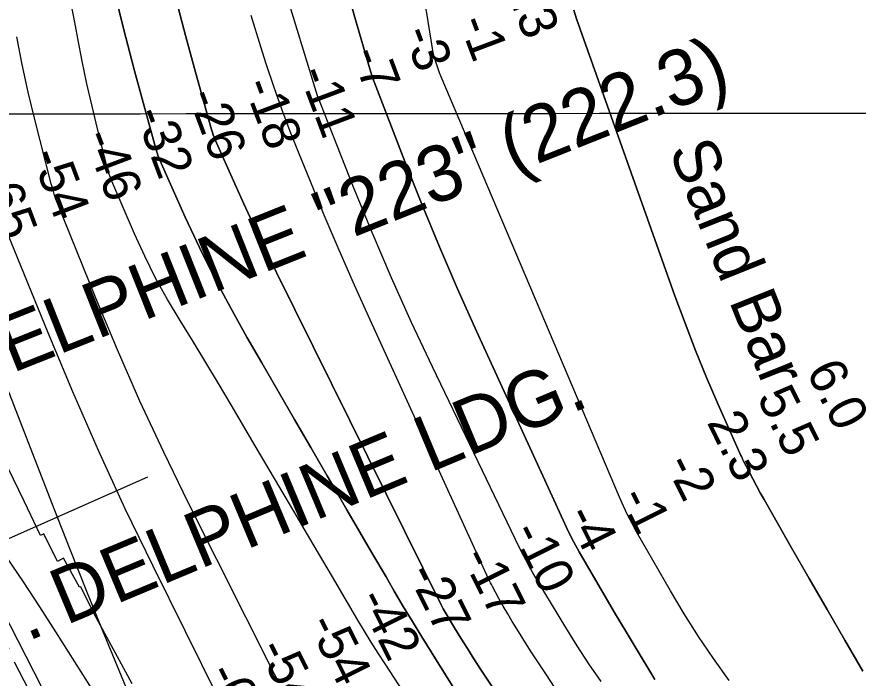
# Model space of a CAD drawing. Extents: x 3297753 to 3335611, y 652252 to 677623.
# Drawn here: x 3308869 to 3310374, y 671780 to 672962 of the extents above; entities that cross this region are included whole.
import ezdxf

# ---------------------------------------------------------------- set-up
doc = ezdxf.new("R2010")
doc.units = 0
for name, color, linetype in [('V-CHAN-NAID', 7, 'Continuous'), ('V-GRID-MAJR', 7, 'Continuous'), ('V-RIVR-EDGE', 7, 'Continuous'), ('V-RIVR-IDEN', 7, 'Continuous'), ('V-RIVR-RANG', 7, 'Continuous'), ('V-RRAP-RVMT', 7, 'Continuous'), ('V-TOPO-DPTH', 7, 'Continuous'), ('V-TOPO-GNAM-IDEN', 7, 'Continuous'), ('V-TOPO-MAJR', 7, 'Continuous'), ('V-TOPO-MINR', 7, 'Continuous'), ('V-TOPO-WATR', 7, 'Continuous')]:
    doc.layers.add(name, color=color, linetype=linetype)

msp = doc.modelspace()

# ---------------------------------------------------------------- linework, layer by layer
at = {"layer": 'V-GRID-MAJR'}
msp.add_spline([(3301861.4, 672784.2), (3307118.4, 672787.6), (3312375.4, 672791.8), (3317632.5, 672796.8), (3322889.5, 672802.5), (3328146.5, 672809), (3333403.5, 672816.3)], degree=3, dxfattribs=at)
at = {"layer": 'V-RIVR-EDGE'}
msp.add_spline([(3307850.6, 675821), (3307850.8, 675819.3), (3307852.4, 675798.5), (3307852.3, 675791.1), (3307856.9, 675791.5), (3307860.2, 675784), (3307858.1, 675766.6), (3307858, 675745.9), (3307859.7, 675743.8), (3307863.4, 675743), (3307863.4, 675739.6), (3307862.9, 675721), (3307866.2, 675694), (3307864.5, 675668.3), (3307864.8, 675653.4), (3307866, 675632.3), (3307866, 675608.2), (3307860.9, 675578), (3307855, 675536.2), (3307852, 675491), (3307848.6, 675457.4), (3307845.6, 675420.9), (3307843.1, 675401.9), (3307841.8, 675387.8), (3307842.2, 675364.6), (3307841.7, 675337.2), (3307844.1, 675320.6), (3307845.7, 675299.9), (3307849, 675263), (3307851.4, 675230.3), (3307851.7, 675205), (3307854.1, 675179.3), (3307857, 675154), (3307856.5, 675138.2), (3307855.7, 675135.8), (3307856.1, 675118.3), (3307855.6, 675111.7), (3307854.4, 675096), (3307852.6, 675077.7), (3307852.2, 675054.1), (3307855.4, 675031.7), (3307862.4, 674991.5), (3307864.8, 674962.5), (3307868.4, 674926), (3307870, 674906.1), (3307872.5, 674875), (3307874.1, 674859.3), (3307876.5, 674843.5), (3307878.9, 674816.1), (3307882.5, 674757.7), (3307886.1, 674712.5), (3307885.7, 674704.2), (3307884.5, 674698), (3307884.4, 674691.8), (3307887.3, 674680.2), (3307887.3, 674669), (3307887.3, 674658.2), (3307885.6, 674651.2), (3307881, 674644.1), (3307881, 674640), (3307886.3, 674626.3), (3307890, 674605.5), (3307895.8, 674578.6), (3307899.4, 674550.8), (3307909.3, 674510.6), (3307914.6, 674482), (3307918.3, 674453.8), (3307918.2, 674440.5), (3307919.9, 674433.9), (3307927.3, 674423.1), (3307927.3, 674417.7), (3307927.2, 674404), (3307928.5, 674400.3), (3307931.8, 674393.2), (3307935.1, 674376.6), (3307944.5, 674357.6), (3307954.9, 674337.2), (3307963.9, 674316.1), (3307975.4, 674271.7), (3307986.5, 674225.2), (3308000.1, 674178.8), (3308007.4, 674148.9), (3308015.2, 674108.3), (3308020.5, 674078.4), (3308024.2, 674072.2), (3308025, 674059.3), (3308025.4, 674039.4), (3308027.8, 673997.2), (3308030.6, 673971.5), (3308027.7, 673955.3), (3308027.2, 673943.3), (3308027.6, 673935.8), (3308029.7, 673925.4), (3308035.5, 673911.8), (3308035.4, 673899.3), (3308034.1, 673873.2), (3308036.1, 673851.2), (3308038.5, 673818.9), (3308041, 673799), (3308046.8, 673788.2), (3308050.5, 673778.3), (3308048.8, 673772.5), (3308048.8, 673761.3), (3308053.7, 673740.5), (3308060.7, 673711.1), (3308069.7, 673678.7), (3308069.7, 673665.1), (3308067.1, 673653.5), (3308067.6, 673650.1), (3308072.9, 673649.3), (3308077.9, 673648.9), (3308080, 673646.4), (3308086.5, 673608.6), (3308091.8, 673582.1), (3308104.6, 673536.5), (3308114.8, 673495), (3308121.4, 673461), (3308123.8, 673446.1), (3308128, 673436.1), (3308140.3, 673406.2), (3308148.9, 673377.2), (3308153, 673357.7), (3308158.3, 673321.2), (3308169, 673273.1), (3308189.1, 673188.1), (3308196.9, 673150.4), (3308208, 673103.9), (3308212, 673079.5), (3308214.1, 673060), (3308216.5, 673045), (3308219, 673035.9), (3308226, 673025.5), (3308228.5, 673016), (3308228.4, 673002.3), (3308230.5, 672996.9), (3308235, 672992.8), (3308235, 672984.5), (3308237.5, 672972.9), (3308242, 672953.4), (3308247.3, 672933.1), (3308253.9, 672910.7), (3308257.6, 672901.5), (3308263.8, 672890.3), (3308276.2, 672865), (3308277.4, 672856.3), (3308278.6, 672850.1), (3308283.2, 672844.3), (3308286.1, 672839.7), (3308286, 672832.2), (3308285.6, 672819), (3308288.5, 672812.3), (3308293.8, 672800.3), (3308303.7, 672777.9), (3308309.9, 672762.5), (3308316.1, 672743), (3308316.4, 672725.6), (3308318.1, 672723.1), (3308323.1, 672717.3), (3308327.6, 672706.1), (3308331.7, 672690.4), (3308330.8, 672679.6), (3308330.4, 672672.1), (3308332.5, 672667.2), (3308337.4, 672658.4), (3308343.6, 672642.7), (3308347.7, 672625.3), (3308355.9, 672595.4), (3308355.9, 672584.6), (3308357.5, 672579.6), (3308362.1, 672570.9), (3308366.6, 672563.5), (3308376.1, 672534), (3308399.6, 672478.4), (3308411.5, 672452.7), (3308418.5, 672435.2), (3308421.8, 672418.7), (3308423, 672410), (3308425.5, 672403.7), (3308428.8, 672397.5), (3308430, 672387.6), (3308434.9, 672375.5), (3308444.4, 672344.8), (3308450.6, 672327), (3308456.8, 672320.8), (3308459.7, 672312.9), (3308465.4, 672288), (3308467.4, 672268.1), (3308473.2, 672249), (3308476.1, 672236.6), (3308485.9, 672214.2), (3308490.1, 672198.8), (3308495.9, 672201.7), (3308496.7, 672193), (3308499.1, 672161.9), (3308505.2, 672134.5), (3308513.9, 672107.6), (3308522.5, 672084.8), (3308527.9, 672082.3), (3308536.2, 672087.2), (3308540.8, 672086.8), (3308539.5, 672083.9), (3308535.8, 672077.7), (3308534.9, 672067.7), (3308534.5, 672059.4), (3308532, 672050.7), (3308533.2, 672047.4), (3308536.9, 672037.9), (3308550.9, 672008.4), (3308564.9, 671974.4), (3308569.9, 671959.5), (3308576.5, 671954.9), (3308585.1, 671932.5), (3308595.9, 671910.5), (3308604.9, 671895.1), (3308605.8, 671888.5), (3308607.8, 671885.2), (3308610.7, 671881), (3308616.5, 671862.8), (3308627.6, 671838.7), (3308640.4, 671816.3), (3308661, 671765.3), (3308673, 671740.8), (3308685.3, 671715.5), (3308698.5, 671692.2), (3308700.2, 671685.6), (3308711.3, 671658.2), (3308728.2, 671627.9), (3308743.1, 671603), (3308758.3, 671575.6), (3308772, 671554.8), (3308775.3, 671548.6), (3308783.1, 671536.2), (3308790.5, 671522.9), (3308793.4, 671519.6), (3308797.2, 671517.1), (3308801.3, 671511.2), (3308803.8, 671502.9), (3308810.8, 671502.1), (3308815.8, 671499.2), (3308833.5, 671474.3), (3308845.1, 671458.5), (3308857.1, 671443.5), (3308870.7, 671429), (3308882.7, 671418.6), (3308908.8, 671397), (3308930.3, 671375.4), (3308944.3, 671361.3), (3308952.6, 671346.7), (3308960.4, 671336.8), (3308966.2, 671331.8), (3308972.8, 671328.9), (3308985.6, 671307.3), (3309001.7, 671282.4), (3309010.8, 671271.6), (3309010.8, 671268.3), (3309008.3, 671266.2), (3309011.6, 671262), (3309018.7, 671250.8), (3309024.8, 671237.1), (3309035.1, 671212.2), (3309059.5, 671169.1), (3309066.5, 671150.8), (3309067.7, 671140.5), (3309071.8, 671135.9), (3309077.2, 671128.4), (3309078.4, 671123), (3309078.4, 671117.6), (3309082.1, 671111.4), (3309089.1, 671092.7), (3309098.6, 671073.2), (3309111.4, 671045), (3309116.4, 671032.2), (3309123.3, 671011), (3309128.7, 670995.6), (3309133.2, 670984.9), (3309144, 670967.4), (3309159.7, 670945.4), (3309169.2, 670933.4), (3309182, 670924.2), (3309188.2, 670917.2), (3309197.7, 670902.2), (3309217.1, 670874.8), (3309231.6, 670859), (3309239.8, 670845.3), (3309244.8, 670840.8), (3309252.2, 670835.3), (3309260.5, 670831.2), (3309275.4, 670817.1), (3309282.4, 670810.4), (3309290.7, 670800), (3309303.1, 670788.4), (3309315.9, 670775.5), (3309335.3, 670751), (3309344.4, 670736.5), (3309351, 670726.5), (3309360.1, 670721.5), (3309375.8, 670704.9), (3309390.7, 670688.7), (3309403.1, 670668.8), (3309415.5, 670646.8), (3309426.7, 670635.1), (3309442.8, 670618.5), (3309454.3, 670603.2), (3309462.2, 670588.6), (3309470.9, 670575.3), (3309476.6, 670563.3), (3309487.4, 670558.3), (3309488.6, 670554.6), (3309489.4, 670550.8), (3309494.8, 670544.2), (3309506.8, 670533.4), (3309523.8, 670518.8), (3309530, 670506), (3309538.6, 670484.8), (3309549.7, 670453.7), (3309551.3, 670440.9), (3309555.5, 670430.9), (3309568.7, 670408.9), (3309577.3, 670396), (3309581.5, 670386.5), (3309581.5, 670383.2), (3309578.6, 670379.9), (3309576.9, 670374.9), (3309582.2, 670364.1), (3309594.6, 670336.7), (3309604.5, 670308.9), (3309606.9, 670296.1), (3309614.4, 670284.8), (3309627.2, 670267), (3309635.5, 670261.6), (3309639.2, 670259.9), (3309638.7, 670250), (3309639.5, 670236.3), (3309641.2, 670228), (3309644.9, 670221.4), (3309656.5, 670208.1), (3309664.3, 670195.6), (3309663.5, 670188.2), (3309663.8, 670176.1), (3309668, 670166.2), (3309673.3, 670159.9), (3309684.1, 670142.9), (3309690.7, 670126.3), (3309700.1, 670102.7), (3309716.7, 670076.5)], degree=3, dxfattribs=at)
at = {"layer": 'V-RIVR-RANG'}
msp.add_line((3307750.1, 671541.1), (3309103.4, 672140.2), dxfattribs=at)
at = {"layer": 'V-RRAP-RVMT'}
for p, q in [((3308882.2, 672096.3), (3308820.5, 672223)), ((3308911.7, 672035.2), (3308882.2, 672096.3)), ((3308917.5, 672038), (3308911.7, 672035.2)), ((3308941.7, 671988.6), (3308917.5, 672038)), ((3308952.7, 671994.7), (3308941.7, 671988.6)), ((3308981.3, 671942.4), (3308952.7, 671994.7)), ((3308983.6, 671943.5), (3308981.3, 671942.4)), ((3309007.2, 671895.1), (3308983.6, 671943.5)), ((3309075.6, 671769.9), (3309007.2, 671895.1))]:
    msp.add_line(p, q, dxfattribs=at)
at = {"layer": 'V-TOPO-DPTH'}
for points in [[(3309041.7, 673017), (3309060.1, 672941.1), (3309079.8, 672865.4), (3309115.2, 672734.9), (3309118.2, 672724.8), (3309121.6, 672714.7), (3309125.4, 672704.8), (3309129.5, 672695.1), (3309170.3, 672604.3), (3309195.9, 672549.7), (3309222.6, 672495.6), (3309251, 672442.4), (3309280.5, 672389.8), (3309307.4, 672343.5), (3309336.7, 672293.1), (3309365.9, 672242.7), (3309395.1, 672192.3), (3309424.3, 672141.9), (3309436.2, 672121.3), (3309459.4, 672081.2), (3309482.7, 672041.1), (3309506.1, 672001), (3309529.5, 671960.9), (3309544.1, 671935.8), (3309560.3, 671908.4), (3309576.7, 671881.1), (3309593.3, 671853.9), (3309610, 671826.9), (3309979.7, 671235.6)], [(3309979.7, 671235.6), (3309610, 671826.9), (3309593.3, 671853.9), (3309576.7, 671881.1), (3309560.3, 671908.4), (3309544.1, 671935.8), (3309529.5, 671960.9), (3309506.1, 672001), (3309482.7, 672041.1), (3309459.4, 672081.2), (3309436.2, 672121.3), (3309424.3, 672141.9), (3309395.1, 672192.3), (3309365.9, 672242.7), (3309336.7, 672293.1), (3309307.4, 672343.5), (3309280.5, 672389.8), (3309251, 672442.4), (3309222.6, 672495.6), (3309195.9, 672549.7), (3309170.3, 672604.3), (3309129.5, 672695.1), (3309125.4, 672704.8), (3309121.6, 672714.7), (3309118.2, 672724.8), (3309115.2, 672734.9), (3309079.8, 672865.4), (3309060.1, 672941.1), (3309041.7, 673017)], [(3309459.4, 673013), (3309473.9, 672961.1), (3309500.3, 672869.5), (3309502.1, 672863.5), (3309504, 672857.6), (3309506, 672851.7), (3309508.2, 672845.9), (3309563.1, 672703.9), (3309593.5, 672627.4), (3309624.9, 672551.2), (3309657.6, 672475.7), (3309691.2, 672400.6), (3309846.4, 672062.2), (3309855.6, 672043.1), (3309865.1, 672024.2), (3309875.1, 672005.6), (3309885.6, 671987.1), (3309936.6, 671900.4), (3309973.3, 671839), (3310010.5, 671777.9)], [(3310010.5, 671777.9), (3309973.3, 671839), (3309936.6, 671900.4), (3309885.6, 671987.1), (3309875.1, 672005.6), (3309865.1, 672024.2), (3309855.6, 672043.1), (3309846.4, 672062.2), (3309691.2, 672400.6), (3309657.6, 672475.7), (3309624.9, 672551.2), (3309593.5, 672627.4), (3309563.1, 672703.9), (3309508.2, 672845.9), (3309506, 672851.7), (3309504, 672857.6), (3309502.1, 672863.5), (3309500.3, 672869.5), (3309473.9, 672961.1), (3309459.4, 673013)], [(3309155.1, 672988.1), (3309170.8, 672928.8), (3309186.9, 672869.6), (3309215.4, 672766.5), (3309217.7, 672759), (3309220.2, 672751.5), (3309223, 672744.2), (3309226, 672736.9), (3309256.5, 672668.8), (3309275.3, 672627.7), (3309294.3, 672586.7), (3309313.8, 672545.9), (3309333.6, 672505.3), (3309628, 671911.1), (3309629.8, 671907.6), (3309631.7, 671904.2), (3309652.1, 671870.1), (3309663.5, 671851.5), (3309675, 671832.9), (3309686.8, 671814.5), (3309698.7, 671796.3), (3309820.8, 671612.2)], [(3309820.8, 671612.2), (3309698.7, 671796.3), (3309686.8, 671814.5), (3309675, 671832.9), (3309663.5, 671851.5), (3309652.1, 671870.1), (3309631.7, 671904.2), (3309629.8, 671907.6), (3309628, 671911.1), (3309333.6, 672505.3), (3309313.8, 672545.9), (3309294.3, 672586.7), (3309275.3, 672627.7), (3309256.5, 672668.8), (3309226, 672736.9), (3309223, 672744.2), (3309220.2, 672751.5), (3309217.7, 672759), (3309215.4, 672766.5), (3309186.9, 672869.6), (3309170.8, 672928.8), (3309155.1, 672988.1)], [(3309865.2, 672974.3), (3309870.3, 672958.5), (3310046.2, 672463.6), (3310064.3, 672414.6), (3310083.1, 672365.8), (3310103, 672317.4), (3310123.7, 672269.4), (3310164.2, 672178.3), (3310165.2, 672176), (3310166.3, 672173.7), (3310167.4, 672171.5), (3310168.5, 672169.2), (3310179, 672148.6), (3310185.4, 672136.2), (3310192, 672123.7), (3310198.8, 672111.4), (3310205.7, 672099.2), (3310254.9, 672013.1), (3310286.6, 671957.9), (3310318.4, 671902.7), (3310350.3, 671847.7), (3310382.3, 671792.7)], [(3310382.3, 671792.7), (3310350.3, 671847.7), (3310318.4, 671902.7), (3310286.6, 671957.9), (3310254.9, 672013.1), (3310205.7, 672099.2), (3310198.8, 672111.4), (3310192, 672123.7), (3310185.4, 672136.2), (3310179, 672148.6), (3310168.5, 672169.2), (3310167.4, 672171.5), (3310166.3, 672173.7), (3310165.2, 672176), (3310164.2, 672178.3), (3310123.7, 672269.4), (3310103, 672317.4), (3310083.1, 672365.8), (3310064.3, 672414.6), (3310046.2, 672463.6), (3309870.3, 672958.5), (3309865.2, 672974.3)], [(3309831, 671764.2), (3309816.6, 671785.7), (3309802.3, 671807.3), (3309788.2, 671829.1), (3309774.3, 671851), (3309763.6, 671868), (3309755.2, 671881.5), (3309747.1, 671895.1), (3309739.1, 671908.8), (3309731.4, 671922.7), (3309719.7, 671943.8), (3309717.9, 671947.2), (3309716.2, 671950.5), (3309714.5, 671953.9), (3309712.9, 671957.3), (3309501.1, 672420.6), (3309473.2, 672482.7), (3309445.8, 672545.1), (3309419.1, 672607.7), (3309393, 672670.6), (3309373.9, 672717.3), (3309358.1, 672757.2), (3309343, 672797.3), (3309328.8, 672837.7), (3309315.3, 672878.4), (3309305.7, 672908.4), (3309288.2, 672964.4)], [(3309831, 671764.2), (3309816.6, 671785.7), (3309802.3, 671807.3), (3309788.2, 671829.1), (3309774.3, 671851), (3309763.6, 671868), (3309755.2, 671881.5), (3309747.1, 671895.1), (3309739.1, 671908.8), (3309731.4, 671922.7), (3309719.7, 671943.8), (3309717.9, 671947.2), (3309716.2, 671950.5), (3309714.5, 671953.9), (3309712.9, 671957.3), (3309501.1, 672420.6), (3309473.2, 672482.7), (3309445.8, 672545.1), (3309419.1, 672607.7), (3309393, 672670.6), (3309373.9, 672717.3), (3309358.1, 672757.2), (3309343, 672797.3), (3309328.8, 672837.7), (3309315.3, 672878.4), (3309305.7, 672908.4), (3309288.2, 672964.4)]]:
    msp.add_lwpolyline(points, dxfattribs=at)
at = {"layer": 'V-TOPO-MAJR'}
msp.add_lwpolyline([(3309567.9, 671744.4), (3309527.8, 671805.6), (3309515.3, 671824.9), (3309503, 671844.4), (3309490.9, 671864), (3309479.1, 671883.8), (3309433.5, 671961.2), (3309399, 672019.7), (3309364.5, 672078.3), (3309330, 672136.8), (3309295.6, 672195.4), (3309252.4, 672268.9), (3309229.9, 672306.7), (3309207.2, 672344.4), (3309184.3, 672381.9), (3309161, 672419.2), (3309138.6, 672457), (3309117.3, 672495.3), (3309097.8, 672534.6), (3309079.5, 672574.5), (3309039.1, 672668.4), (3309036.4, 672675.2), (3309033.9, 672682), (3309031.7, 672689), (3309029.8, 672696), (3309013.3, 672762.1), (3309003.7, 672802.3), (3308994.5, 672842.7), (3308986.1, 672883.1), (3308978.1, 672923.7), (3308973.8, 672946.4), (3308963.9, 672998.4)], dxfattribs=at)
at = {"layer": 'V-TOPO-MINR'}
for points in [[(3310143.4, 671775.9), (3310115.4, 671814.9), (3310088.3, 671854.5), (3310062.7, 671895.1), (3310038.1, 671936.3), (3309977.8, 672041.6), (3309969.5, 672056.7), (3309961.5, 672072.1), (3309954.1, 672087.7), (3309947.1, 672103.5), (3309628.1, 672855.1), (3309625.3, 672862.1), (3309622.6, 672869.2), (3309620.2, 672876.4), (3309617.9, 672883.7), (3309615.9, 672891), (3309614.1, 672898.4), (3309612.6, 672905.8), (3309611.3, 672913.3), (3309571.4, 673160.7)], [(3309979.7, 671235.6), (3309610, 671826.9), (3309593.3, 671853.9), (3309576.7, 671881.1), (3309560.3, 671908.4), (3309544.1, 671935.8), (3309529.5, 671960.9), (3309506.1, 672001), (3309482.7, 672041.1), (3309459.4, 672081.2), (3309436.2, 672121.3), (3309424.3, 672141.9), (3309395.1, 672192.3), (3309365.9, 672242.7), (3309336.7, 672293.1), (3309307.4, 672343.5), (3309280.5, 672389.8), (3309251, 672442.4), (3309222.6, 672495.6), (3309195.9, 672549.7), (3309170.3, 672604.3), (3309129.5, 672695.1), (3309125.4, 672704.8), (3309121.6, 672714.7), (3309118.2, 672724.8), (3309115.2, 672734.9), (3309079.8, 672865.4), (3309060.1, 672941.1), (3309041.7, 673017)], [(3310010.5, 671777.9), (3309973.3, 671839), (3309936.6, 671900.4), (3309885.6, 671987.1), (3309875.1, 672005.6), (3309865.1, 672024.2), (3309855.6, 672043.1), (3309846.4, 672062.2), (3309691.2, 672400.6), (3309657.6, 672475.7), (3309624.9, 672551.2), (3309593.5, 672627.4), (3309563.1, 672703.9), (3309508.2, 672845.9), (3309506, 672851.7), (3309504, 672857.6), (3309502.1, 672863.5), (3309500.3, 672869.5), (3309473.9, 672961.1), (3309459.4, 673013)], [(3309914.5, 671773.8), (3309892.5, 671805.5), (3309871.4, 671837.8), (3309851, 671870.5), (3309799.9, 671955.1), (3309791.6, 671969.4), (3309783.5, 671983.8), (3309775.9, 671998.4), (3309768.5, 672013.2), (3309612.6, 672336.3), (3309575.3, 672415.8), (3309539.2, 672495.8), (3309504.8, 672576.6), (3309471.5, 672657.8), (3309412.6, 672806.1), (3309409.8, 672813.6), (3309407, 672821.2), (3309404.5, 672828.8), (3309402, 672836.4), (3309350.4, 673006.5)], [(3309820.8, 671612.2), (3309698.7, 671796.3), (3309686.8, 671814.5), (3309675, 671832.9), (3309663.5, 671851.5), (3309652.1, 671870.1), (3309631.7, 671904.2), (3309629.8, 671907.6), (3309628, 671911.1), (3309333.6, 672505.3), (3309313.8, 672545.9), (3309294.3, 672586.7), (3309275.3, 672627.7), (3309256.5, 672668.8), (3309226, 672736.9), (3309223, 672744.2), (3309220.2, 672751.5), (3309217.7, 672759), (3309215.4, 672766.5), (3309186.9, 672869.6), (3309170.8, 672928.8), (3309155.1, 672988.1)], [(3309831, 671764.2), (3309816.6, 671785.7), (3309802.3, 671807.3), (3309788.2, 671829.1), (3309774.3, 671851), (3309763.6, 671868), (3309755.2, 671881.5), (3309747.1, 671895.1), (3309739.1, 671908.8), (3309731.4, 671922.7), (3309719.7, 671943.8), (3309717.9, 671947.2), (3309716.2, 671950.5), (3309714.5, 671953.9), (3309712.9, 671957.3), (3309501.1, 672420.6), (3309473.2, 672482.7), (3309445.8, 672545.1), (3309419.1, 672607.7), (3309393, 672670.6), (3309373.9, 672717.3), (3309358.1, 672757.2), (3309343, 672797.3), (3309328.8, 672837.7), (3309315.3, 672878.4), (3309305.7, 672908.4), (3309288.2, 672964.4)], [(3309336.2, 671775.9), (3309330.2, 671787.2), (3309175.7, 672094.2), (3309131.8, 672184.3), (3309089.4, 672275.1), (3309049.2, 672366.9), (3309010.5, 672459.3), (3308942.5, 672627.6), (3308939.1, 672636.5), (3308936, 672645.5), (3308933.2, 672654.6), (3308930.6, 672663.8), (3308901.2, 672778.4), (3308889.4, 672827.6), (3308878.5, 672877), (3308869, 672926.6)], [(3309228.9, 671746.7), (3309112.9, 671980), (3309063.1, 672083), (3309014.9, 672186.8), (3308969.1, 672291.6), (3308924.9, 672397.1), (3308847.1, 672588.8)], [(3309104.9, 671666.2), (3309051.9, 671793.8), (3309022.3, 671865.8), (3308993, 671937.9), (3308964.2, 672010.3), (3308935.7, 672082.7), (3308752.7, 672552.7)], [(3308758.8, 672065.7), (3308996.7, 671601), (3308998.4, 671597.8), (3309000.1, 671594.6), (3309001.9, 671591.5), (3309003.7, 671588.4), (3309017.8, 671565.5), (3309020.8, 671560.8), (3309024, 671556.2), (3309027.4, 671551.7), (3309030.9, 671547.4), (3309034.6, 671543.2), (3309594.9, 670863.7), (3309602.6, 670851.4), (3309610.7, 670839.4), (3309619.3, 670827.8), (3309628.4, 670816.5), (3309932.1, 670456.8)], [(3308850.2, 671996.7), (3308880.2, 671952.5), (3308909.6, 671907.8), (3308938.5, 671862.9), (3309074.4, 671648.3)], [(3308864.2, 671809), (3308967.5, 671610.4), (3308974.3, 671597.8), (3308981.3, 671585.3), (3308988.5, 671573), (3308996, 671560.8), (3309046.1, 671481.5), (3309058.3, 671463), (3309070.9, 671444.9), (3309084.1, 671427.3), (3309097.9, 671410), (3309112.1, 671393.1), (3309126.6, 671376.5), (3309141.5, 671360.2), (3309156.6, 671344.1), (3309515, 670925.3), (3309557.8, 670868.8), (3309573.8, 670848), (3309590.1, 670827.5), (3309606.8, 670807.3), (3309623.7, 670787.4), (3310064.1, 670277.7)]]:
    msp.add_lwpolyline(points, dxfattribs=at)
at = {"layer": 'V-TOPO-WATR'}
msp.add_lwpolyline([(3310382.3, 671792.7), (3310350.3, 671847.7), (3310318.4, 671902.7), (3310286.6, 671957.9), (3310254.9, 672013.1), (3310205.7, 672099.2), (3310198.8, 672111.4), (3310192, 672123.7), (3310185.4, 672136.2), (3310179, 672148.6), (3310168.5, 672169.2), (3310167.4, 672171.5), (3310166.3, 672173.7), (3310165.2, 672176), (3310164.2, 672178.3), (3310123.7, 672269.4), (3310103, 672317.4), (3310083.1, 672365.8), (3310064.3, 672414.6), (3310046.2, 672463.6), (3309870.3, 672958.5), (3309865.2, 672974.3)], dxfattribs=at)

# ---------------------------------------------------------------- texts
at = {"layer": 'V-CHAN-NAID'}
msp.add_text('ST. DELPHINE "223" (222.3)', height=100, rotation=21.7054, dxfattribs=at).set_placement((3308543.1, 672198.4))
at = {"layer": 'V-RIVR-IDEN'}
msp.add_text('Sand Bar', height=83, rotation=291.7948, dxfattribs=at).set_placement((3310034.8, 672724))
at = {"layer": 'V-RIVR-RANG'}
for s, rotation, p in [('1.3', 290.592, (3309735.1, 673034.7)), ('-1', 290.592, (3309659.1, 672952.8)), ('-3', 290.592, (3309559.3, 672933.9)), ('-7', 290.592, (3309466.7, 672896.3)), ('-11', 290.592, (3309372.6, 672862.3)), ('-18', 290.592, (3309273.8, 672841)), ('-26', 290.592, (3309174.3, 672821.3)), ('-32', 290.592, (3309079.5, 672789.3)), ('-46', 290.592, (3308988.1, 672748.5)), ('-54', 290.592, (3308893.7, 672715.3)), ('-65', 290.592, (3308800.1, 672680.1)), ('6.0', 296.55, (3310280.4, 672329)), ('5.5', 296.55, (3310192.1, 672281.9)), ('2.3', 296.55, (3310102.6, 672237.4)), ('-2', 296.55, (3310028, 672163)), ('-1', 296.55, (3309945.8, 672103.6)), ('-4', 296.55, (3309850.2, 672071.4)), ('-10', 296.55, (3309753.3, 672041.6)), ('-17', 296.55, (3309663.9, 671996.6)), ('-27', 296.55, (3309566.8, 671967.3)), ('-42', 296.55, (3309477.6, 671922.1)), ('-54', 296.55, (3309388.4, 671876.9)), ('-54', 296.55, (3309298.8, 671832.4)), ('-63', 296.55, (3309208.7, 671789.1))]:
    msp.add_text(s, height=67, rotation=rotation, dxfattribs=at).set_placement(p)
at = {"layer": 'V-TOPO-GNAM-IDEN'}
msp.add_text('ST. DELPHINE LDG.', height=100, rotation=22.7309, dxfattribs=at).set_placement((3308730.7, 671779.4))

doc.saveas('drawing.dxf')
